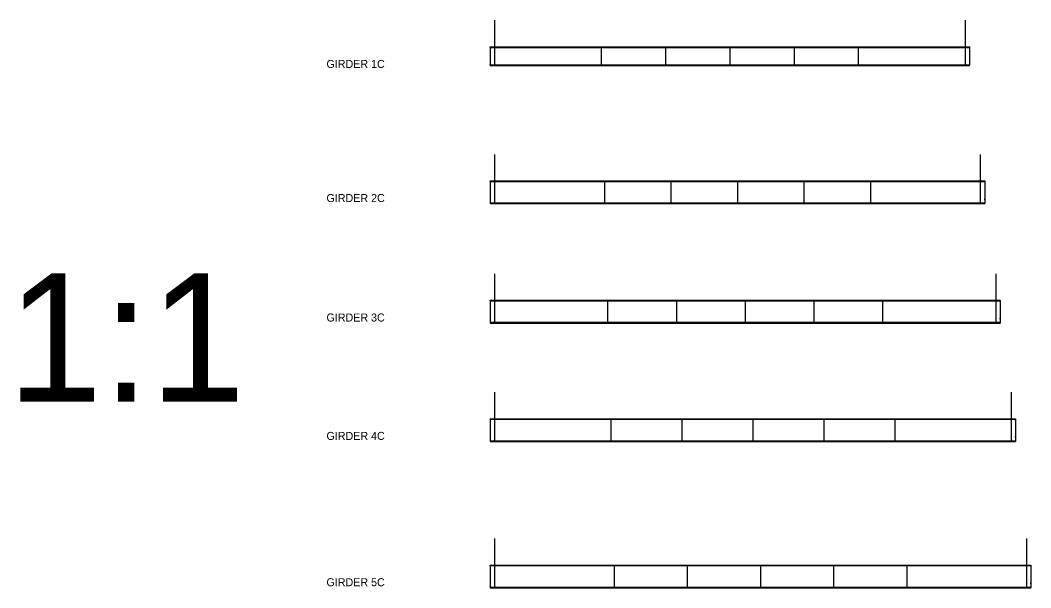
# Model space of a CAD drawing. Extents: x -383 to -161, y -356 to -99.
# Drawn here: x -382.9 to -193.4, y -356.4 to -250.1 of the extents above; entities that cross this region are included whole.
import ezdxf

# ---------------------------------------------------------------- set-up
doc = ezdxf.new("R2010")
doc.units = 0
for name, color, linetype in [('BR_CENTER LINES', 7, 'Continuous'), ('BR_STRUCTURAL STEEL', 7, 'Continuous'), ('BR_TEXT', 7, 'Continuous')]:
    doc.layers.add(name, color=color, linetype=linetype)

msp = doc.modelspace()

# ---------------------------------------------------------------- linework, layer by layer
at = {"layer": 'BR_CENTER LINES'}
for p, q in [((-293.95, -250.14), (-293.95, -255.22)), ((-205.77, -250.14), (-205.77, -255.22)), ((-293.95, -275.26), (-293.95, -280.34)), ((-202.9, -275.26), (-202.9, -280.34)), ((-293.95, -297.62), (-293.95, -302.7)), ((-200.02, -297.62), (-200.02, -302.7)), ((-293.95, -319.79), (-293.95, -324.87)), ((-197.15, -319.79), (-197.15, -324.87)), ((-293.95, -347.19), (-293.95, -352.27)), ((-194.27, -347.19), (-194.27, -352.27))]:
    msp.add_line(p, q, dxfattribs=at)
at = {"layer": 'BR_STRUCTURAL STEEL'}
for p, q in [((-294.79, -255.22), (-294.79, -255.1)), ((-294.79, -255.1), (-204.94, -255.1)), ((-294.79, -255.22), (-204.94, -255.22)), ((-294.79, -255.22), (-294.79, -258.47)), ((-293.95, -255.22), (-293.95, -258.47)), ((-273.95, -255.22), (-273.95, -258.47)), ((-261.91, -255.22), (-261.91, -258.47)), ((-249.86, -255.22), (-249.86, -258.47)), ((-237.82, -255.22), (-237.82, -258.47)), ((-225.77, -255.22), (-225.77, -258.47)), ((-205.77, -255.22), (-205.77, -258.47)), ((-204.94, -255.1), (-204.94, -255.22)), ((-204.94, -255.22), (-204.94, -258.47)), ((-294.79, -258.47), (-204.94, -258.47)), ((-294.79, -258.64), (-294.79, -258.47)), ((-294.79, -258.64), (-204.94, -258.64)), ((-204.94, -258.64), (-204.94, -258.47)), ((-294.79, -280.34), (-294.79, -280.23)), ((-294.79, -280.23), (-202.06, -280.23)), ((-202.06, -280.23), (-202.06, -280.34)), ((-294.79, -280.34), (-202.06, -280.34)), ((-294.79, -280.34), (-294.79, -284.34)), ((-293.95, -280.34), (-293.95, -284.34)), ((-273.35, -280.34), (-273.35, -284.34)), ((-260.89, -280.34), (-260.89, -284.34)), ((-248.42, -280.34), (-248.42, -284.34)), ((-235.96, -280.34), (-235.96, -284.34)), ((-223.5, -280.34), (-223.5, -284.34)), ((-202.9, -280.34), (-202.9, -284.34)), ((-202.06, -280.34), (-202.06, -284.34)), ((-202.06, -283.75), (-202.06, -283.59)), ((-294.79, -284.34), (-202.06, -284.34)), ((-294.79, -284.34), (-294.79, -284.48)), ((-294.79, -284.48), (-202.06, -284.48)), ((-202.06, -284.34), (-202.06, -284.48)), ((-294.79, -302.7), (-294.79, -302.59)), ((-294.79, -302.59), (-199.19, -302.59)), ((-294.79, -302.7), (-199.19, -302.7)), ((-294.79, -302.7), (-294.79, -306.7)), ((-293.95, -302.7), (-293.95, -306.7)), ((-272.76, -302.7), (-272.76, -306.7)), ((-259.87, -302.7), (-259.87, -306.7)), ((-246.99, -302.7), (-246.99, -306.7)), ((-234.1, -302.7), (-234.1, -306.7)), ((-221.22, -302.7), (-221.22, -306.7)), ((-200.02, -302.7), (-200.02, -306.7)), ((-199.19, -302.59), (-199.19, -302.7)), ((-199.19, -302.7), (-199.19, -306.7)), ((-294.79, -306.7), (-199.19, -306.7)), ((-294.79, -306.7), (-294.79, -306.84)), ((-294.79, -306.84), (-199.19, -306.84)), ((-199.19, -306.11), (-199.19, -305.95)), ((-199.19, -306.7), (-199.19, -306.84)), ((-294.79, -324.87), (-294.79, -324.77)), ((-294.79, -324.77), (-196.32, -324.77)), ((-294.79, -324.87), (-196.32, -324.87)), ((-294.79, -324.87), (-294.79, -328.87)), ((-293.95, -324.87), (-293.95, -328.87)), ((-272.16, -324.87), (-272.16, -328.87)), ((-258.85, -324.87), (-258.85, -328.87)), ((-245.55, -324.87), (-245.55, -328.87)), ((-232.25, -324.87), (-232.25, -328.87)), ((-218.94, -324.87), (-218.94, -328.87)), ((-197.15, -324.87), (-197.15, -328.87)), ((-196.32, -324.77), (-196.32, -324.87)), ((-196.32, -324.87), (-196.32, -328.87)), ((-294.79, -328.87), (-196.32, -328.87)), ((-294.79, -328.87), (-294.79, -329.02)), ((-294.79, -329.02), (-196.32, -329.02)), ((-196.32, -328.29), (-196.32, -328.12)), ((-196.32, -328.87), (-196.32, -329.02)), ((-294.79, -352.27), (-294.79, -352.16)), ((-294.79, -352.16), (-193.44, -352.16)), ((-294.79, -352.27), (-193.44, -352.27)), ((-294.79, -352.27), (-294.79, -356.27)), ((-293.95, -352.27), (-293.95, -356.27)), ((-271.56, -352.27), (-271.56, -356.27)), ((-257.84, -352.27), (-257.84, -356.27)), ((-244.11, -352.27), (-244.11, -356.27)), ((-230.39, -352.27), (-230.39, -356.27)), ((-216.67, -352.27), (-216.67, -356.27)), ((-194.27, -352.27), (-194.27, -356.27)), ((-193.44, -352.16), (-193.44, -352.27)), ((-193.44, -352.27), (-193.44, -356.27)), ((-193.44, -355.68), (-193.44, -355.52)), ((-294.79, -356.27), (-193.44, -356.27)), ((-294.79, -356.27), (-294.79, -356.41)), ((-294.79, -356.41), (-193.44, -356.41)), ((-193.44, -356.27), (-193.44, -356.41))]:
    msp.add_line(p, q, dxfattribs=at)

# ---------------------------------------------------------------- texts
at = {"layer": 'BR_TEXT'}
for s, height, p in [('GIRDER 1C', 1.5, (-325.45, -259.08)), ('GIRDER 2C', 1.5, (-325.45, -284.19)), ('1:1', 24, (-385.3, -321.55)), ('GIRDER 3C', 1.5, (-325.45, -306.56)), ('GIRDER 4C', 1.5, (-325.45, -328.73)), ('GIRDER 5C', 1.5, (-325.45, -356.13))]:
    msp.add_text(s, height=height, dxfattribs=at).set_placement(p)

doc.saveas('drawing.dxf')
